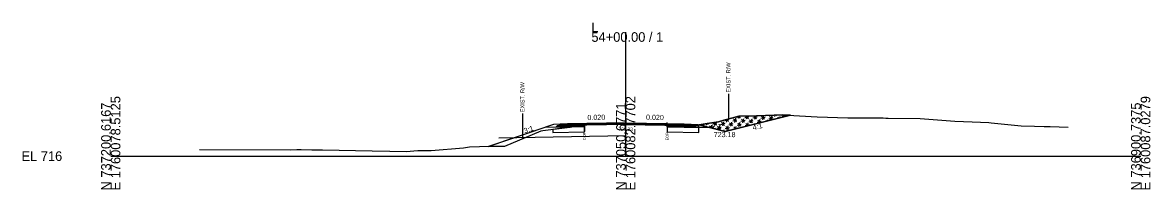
# Model space of a CAD drawing. Extents: x -26 to 4303, y -10 to 9577.
# Drawn here: x 3974.3 to 4302.8, y 3990.3 to 4038.9 of the extents above; entities that cross this region are included whole.
import ezdxf

# ---------------------------------------------------------------- set-up
doc = ezdxf.new("R2010")
doc.units = 0
for name, color, linetype in [('Default', 7, 'Continuous'), ('Exist CMT Pavement', 7, 'Continuous'), ('Old_Level_2', 7, 'Continuous'), ('Pattern 3', 7, 'Continuous'), ('Prop CMT Conc Surface', 7, 'Continuous'), ('Prop CMT Concrete Structures', 7, 'Continuous'), ('Prop CMT Concrete Wall', 7, 'Continuous'), ('Prop CMT Pvmt Course 1', 7, 'Continuous'), ('Prop CMT Pvmt Course 1 CG', 7, 'Continuous'), ('Prop CMT Pvmt Course 2', 7, 'Continuous'), ('Prop CMT Pvmt Course 2 Wedge', 7, 'Continuous'), ('Prop CMT Pvmt Course 3', 7, 'Continuous'), ('Prop CMT Pvmt Surface', 7, 'Continuous'), ('Prop CMT Pvmt Surface Shoulder', 7, 'Continuous'), ('Prop CMT Pvmt Wedge Surface 1', 7, 'Continuous'), ('Prop CMT Pvmt Wedge Surface 2', 7, 'Continuous'), ('Prop CMT Pvmt Wedge Surface 3', 7, 'Continuous'), ('Prop CMT Shld Paved Course 1', 7, 'Continuous'), ('Prop CMT Shld Paved Course 2', 7, 'Continuous'), ('Prop CMT Shld Paved Course 3', 7, 'Continuous'), ('Prop CMT Slope Grass', 7, 'Continuous'), ('Prop CMT Subgrade Earthwork', 7, 'Continuous'), ('Prop Road Sect_ Recs - UC Shallow (Outline)', 7, 'Continuous'), ('Prop Shade Light', 7, 'Continuous'), ('Prop XS DDE Elevations', 7, 'Continuous'), ('Prop XS Ditch Standard Text', 7, 'Continuous'), ('Prop XS Hydro Elevations', 7, 'Continuous'), ('Prop XS SE Text', 7, 'Continuous'), ('Prop XS Side Slope Text', 7, 'Continuous'), ('Prop XS Wedging', 7, 'Continuous'), ('Scratch_Level_2', 7, 'Continuous'), ('Scratch_Level_6', 7, 'Continuous')]:
    doc.layers.add(name, color=color, linetype=linetype)

msp = doc.modelspace()

# ---------------------------------------------------------------- linework, layer by layer
at = {"layer": 'Exist CMT Pavement'}
for points in [[(4150, 4009.72), (4133, 4009.38)], [(4150, 4009.72), (4167, 4009.38)]]:
    msp.add_lwpolyline(points, dxfattribs=at)
at = {"layer": 'Old_Level_2'}
for p, q in [((4150, 4000), (4150, 4036.09)), ((4150, 4000), (4150, 4036.09)), ((4000, 4000), (4150, 4000)), ((4000, 4000), (4150, 4000)), ((4150, 4000), (4300, 4000)), ((4150, 4000), (4300, 4000))]:
    msp.add_line(p, q, dxfattribs=at)
at = {"layer": 'Pattern 3'}
for p, q in [((4182.33, 4011.37), (4183.33, 4011.64)), ((4182.96, 4011.63), (4182.77, 4010.93)), ((4182.85, 4011.61), (4183.37, 4011.09)), ((4184.68, 4011.25), (4185.89, 4011.58)), ((4185.02, 4011.68), (4185.73, 4010.97)), ((4185.36, 4011.69), (4185.12, 4010.81)), ((4187.04, 4011.14), (4188.25, 4011.46)), ((4187.21, 4011.73), (4188.09, 4010.86)), ((4187.76, 4011.75), (4187.48, 4010.69)), ((4189.56, 4011.62), (4190.44, 4010.74)), ((4190.16, 4011.78), (4189.84, 4010.58)), ((4190.99, 4011.82), (4190.96, 4011.7)), ((4191.91, 4011.5), (4192.79, 4010.63)), ((4192.52, 4011.66), (4192.2, 4010.48)), ((4193.41, 4011.93), (4193.31, 4011.58)), ((4193.71, 4011.94), (4193.92, 4011.74)), ((4194.27, 4011.38), (4194.58, 4011.08)), ((4194.87, 4011.55), (4194.76, 4011.12)), ((4195.23, 4011.9), (4195.72, 4012.03)), ((4195.82, 4012.03), (4195.67, 4011.46)), ((4195.87, 4012.02), (4196.27, 4011.62)), ((4135.32, 4008.74), (4135.42, 4008.64)), ((4135.52, 4008.78), (4135.49, 4008.64)), ((4135.69, 4008.64), (4136.08, 4008.75)), ((4137.39, 4008.91), (4137.62, 4008.68)), ((4137.95, 4008.93), (4137.89, 4008.69)), ((4162.47, 4009.02), (4162.38, 4008.69)), ((4162.87, 4008.97), (4162.99, 4008.86)), ((4164.79, 4008.77), (4164.75, 4008.64)), ((4172.06, 4008.98), (4172.14, 4008.9)), ((4172.67, 4009.14), (4172.57, 4008.79)), ((4173.03, 4008.67), (4173.11, 4008.69)), ((4173.57, 4009.45), (4173.46, 4009.05)), ((4173.78, 4009.49), (4174.06, 4009.21)), ((4174.42, 4008.86), (4175.12, 4008.15)), ((4174.48, 4008.31), (4175.46, 4008.58)), ((4175.02, 4009.02), (4174.81, 4008.23)), ((4175.38, 4009.37), (4176.58, 4009.7)), ((4175.71, 4009.8), (4176.42, 4009.09)), ((4176.07, 4009.86), (4175.82, 4008.93)), ((4176.61, 4008.13), (4177.82, 4008.46)), ((4176.77, 4008.74), (4177.66, 4007.85)), ((4177.38, 4008.9), (4177.06, 4007.69)), ((4177.73, 4009.25), (4178.94, 4009.58)), ((4177.89, 4009.86), (4178.78, 4008.97)), ((4178.5, 4010.02), (4178.17, 4008.81)), ((4178.85, 4010.37), (4180.06, 4010.7)), ((4178.97, 4008.02), (4180.18, 4008.34)), ((4179.13, 4008.62), (4180.02, 4007.74)), ((4179.49, 4010.68), (4179.29, 4009.93)), ((4179.35, 4010.64), (4179.9, 4010.09)), ((4179.73, 4008.78), (4179.41, 4007.57)), ((4180.09, 4009.14), (4181.3, 4009.46)), ((4180.25, 4009.74), (4181.13, 4008.85)), ((4180.85, 4009.9), (4180.53, 4008.69)), ((4181.21, 4010.25), (4182.41, 4010.58)), ((4181.33, 4007.9), (4182.53, 4008.22)), ((4181.37, 4010.86), (4182.25, 4009.97)), ((4181.49, 4008.5), (4182.05, 4007.94)), ((4181.97, 4011.02), (4181.65, 4009.81)), ((4182.09, 4008.66), (4181.89, 4007.9)), ((4182.44, 4009.02), (4183.65, 4009.34)), ((4182.61, 4009.62), (4183.49, 4008.74)), ((4183.21, 4009.78), (4182.89, 4008.57)), ((4183.56, 4010.14), (4184.77, 4010.46)), ((4183.73, 4010.74), (4184.61, 4009.86)), ((4184.33, 4010.9), (4184.01, 4009.69)), ((4184.45, 4008.54), (4184.45, 4008.54)), ((4184.8, 4008.9), (4186.01, 4009.22)), ((4184.96, 4009.5), (4185.63, 4008.84)), ((4185.57, 4009.66), (4185.33, 4008.76)), ((4185.92, 4010.02), (4187.13, 4010.34)), ((4186.08, 4010.62), (4186.97, 4009.74)), ((4186.69, 4010.78), (4186.36, 4009.58)), ((4187.32, 4009.38), (4187.42, 4009.29)), ((4187.92, 4009.55), (4187.89, 4009.4)), ((4188.28, 4009.9), (4189.48, 4010.22)), ((4188.44, 4010.5), (4189.21, 4009.73)), ((4189.04, 4010.66), (4188.76, 4009.62)), ((4189.4, 4011.02), (4190.6, 4011.34)), ((4190.8, 4010.38), (4191, 4010.18)), ((4191.4, 4010.55), (4191.32, 4010.26)), ((4191.75, 4010.9), (4192.96, 4011.22)), ((4178.01, 4007.5), (4178.11, 4007.4)), ((4178.62, 4007.66), (4178.52, 4007.3)), ((4178.95, 4007.19), (4179.06, 4007.22))]:
    msp.add_line(p, q, dxfattribs=at)
for points in [[(4197.95, 4011.92), (4179, 4007.18), (4171.4, 4009.08), (4173.75, 4009.49), (4176.98, 4010), (4178.62, 4010.43), (4179.73, 4010.74), (4182.93, 4011.63), (4188.12, 4011.76), (4190.67, 4011.81), (4195.71, 4012.03), (4197.23, 4011.96)], [(4134.06, 4008.53), (4137.95, 4008.61), (4137.95, 4009.19)], [(4167.16, 4008.5), (4162.07, 4008.61), (4162.07, 4009.06)], [(4171.31, 4008.42), (4171.31, 4009.07), (4167.95, 4008.49)]]:
    msp.add_lwpolyline(points, close=True, dxfattribs=at)
at = {"layer": 'Prop CMT Conc Surface'}
for points in [[(4137.95, 4009.23), (4133, 4009.13)], [(4133, 4009.13), (4133, 4008.92)], [(4133, 4008.92), (4137.95, 4009.02)], [(4137.95, 4009.02), (4137.95, 4009.23)], [(4162.07, 4009.02), (4162.07, 4009.23)], [(4162.07, 4009.23), (4167, 4009.13)], [(4167, 4008.92), (4162.07, 4009.02)], [(4167, 4009.13), (4167, 4008.92)]]:
    msp.add_lwpolyline(points, dxfattribs=at)
at = {"layer": 'Prop CMT Concrete Structures'}
for points in [[(4133, 4009.13), (4133, 4009.38)], [(4137.95, 4009.23), (4133, 4009.13)], [(4150, 4009.6), (4137.95, 4009.36)], [(4137.95, 4009.36), (4137.95, 4009.23)], [(4150, 4009.6), (4162.07, 4009.36)], [(4162.07, 4009.36), (4162.07, 4009.23)], [(4162.07, 4009.23), (4167, 4009.13)], [(4167, 4009.13), (4167, 4009.38)]]:
    msp.add_lwpolyline(points, dxfattribs=at)
at = {"layer": 'Prop CMT Pvmt Course 1'}
for points in [[(4137.95, 4009.02), (4133, 4008.92)], [(4133, 4008.92), (4133, 4008.59)], [(4133, 4008.59), (4137.95, 4008.69)], [(4137.95, 4008.69), (4137.95, 4009.02)], [(4162.07, 4009.02), (4167, 4008.92)], [(4162.07, 4008.69), (4162.07, 4009.02)], [(4167, 4008.59), (4162.07, 4008.69)], [(4167, 4008.92), (4167, 4008.59)]]:
    msp.add_lwpolyline(points, dxfattribs=at)
at = {"layer": 'Prop CMT Pvmt Course 2'}
for points in [[(4133, 4009.38), (4131, 4009.34), (4130.74, 4009.09)], [(4130.74, 4009.09), (4133, 4009.13)], [(4133, 4009.13), (4133, 4009.38)], [(4167, 4009.38), (4169, 4009.34), (4169.26, 4009.09)], [(4167, 4009.13), (4167, 4009.38)], [(4169.26, 4009.09), (4167, 4009.13)]]:
    msp.add_lwpolyline(points, dxfattribs=at)
at = {"layer": 'Prop CMT Pvmt Course 2 Wedge'}
for points in [[(4169, 4009.34), (4171, 4009.18), (4179, 4007.18), (4197.95, 4011.92)], [(4131, 4009.34), (4129, 4009.18), (4110.1, 4002.85)]]:
    msp.add_lwpolyline(points, dxfattribs=at)
at = {"layer": 'Prop CMT Pvmt Course 3'}
for points in [[(4133, 4009.13), (4130.74, 4009.09), (4130.53, 4008.87)], [(4130.53, 4008.87), (4133, 4008.92)], [(4133, 4008.92), (4133, 4009.13)], [(4167, 4009.13), (4169.26, 4009.09), (4169.47, 4008.87)], [(4167, 4008.92), (4167, 4009.13)], [(4169.47, 4008.87), (4167, 4008.92)]]:
    msp.add_lwpolyline(points, dxfattribs=at)
at = {"layer": 'Prop CMT Pvmt Surface'}
for points in [[(4150, 4009.47), (4133, 4009.13)], [(4133, 4009.13), (4133, 4009.38)], [(4150, 4009.47), (4167, 4009.13)], [(4167, 4009.13), (4167, 4009.38)]]:
    msp.add_lwpolyline(points, dxfattribs=at)
at = {"layer": 'Prop CMT Pvmt Surface Shoulder'}
for points in [[(4137.95, 4009.19), (4138.02, 4009.2), (4139.05, 4009.23), (4139.4, 4009.23), (4140.63, 4009.24), (4141.27, 4009.24), (4141.92, 4009.25), (4143.1, 4009.27), (4144.42, 4009.3), (4145.53, 4009.31), (4146.93, 4009.32), (4147.96, 4009.32), (4149.43, 4009.34), (4149.59, 4009.34), (4150, 4009.33)], [(4150, 4009.33), (4150.4, 4009.32), (4151.53, 4009.31), (4151.93, 4009.3), (4152.83, 4009.29), (4154.43, 4009.27), (4155.26, 4009.26), (4156.93, 4009.22), (4157.69, 4009.2), (4159.43, 4009.16), (4159.6, 4009.16), (4160.97, 4009.11), (4161.48, 4009.09), (4161.88, 4009.08), (4162.07, 4009.06)]]:
    msp.add_lwpolyline(points, dxfattribs=at)
at = {"layer": 'Prop CMT Pvmt Wedge Surface 1'}
for p, q in [((4133.02, 4008.47), (4126.47, 4008.33)), ((4137.95, 4008.56), (4133.02, 4008.47)), ((4162.07, 4008.56), (4166.98, 4008.47)), ((4166.98, 4008.47), (4174.47, 4008.32))]:
    msp.add_line(p, q, dxfattribs=at)
for points in [[(4137.95, 4008.56), (4137.95, 4009.19)], [(4162.07, 4008.56), (4162.07, 4009.06)]]:
    msp.add_lwpolyline(points, dxfattribs=at)
at = {"layer": 'Prop CMT Pvmt Wedge Surface 2'}
for points in [[(4137.95, 4009.36), (4138.02, 4009.36), (4139.05, 4009.38), (4139.4, 4009.38), (4140.63, 4009.41), (4141.27, 4009.42), (4141.92, 4009.44), (4143.1, 4009.46), (4144.42, 4009.49), (4145.53, 4009.51), (4146.93, 4009.54), (4147.96, 4009.56), (4149.43, 4009.59), (4149.59, 4009.59), (4150, 4009.6)], [(4150, 4009.47), (4149.59, 4009.46), (4149.43, 4009.46), (4147.96, 4009.43), (4146.93, 4009.41), (4145.53, 4009.38), (4144.42, 4009.36), (4143.1, 4009.33), (4141.92, 4009.31), (4141.27, 4009.3), (4140.63, 4009.28), (4139.4, 4009.26), (4139.05, 4009.25), (4138.02, 4009.23), (4137.95, 4009.23)], [(4137.95, 4009.23), (4137.95, 4009.36)], [(4150, 4009.6), (4150, 4009.47)], [(4150, 4009.6), (4150.4, 4009.59), (4151.53, 4009.57), (4151.93, 4009.56), (4152.83, 4009.54), (4154.43, 4009.51), (4155.26, 4009.49), (4156.93, 4009.46), (4157.69, 4009.44), (4159.43, 4009.41), (4159.6, 4009.4), (4160.97, 4009.38), (4161.48, 4009.37), (4161.88, 4009.36), (4162.07, 4009.36)], [(4162.07, 4009.23), (4161.88, 4009.23), (4161.48, 4009.24), (4160.97, 4009.25), (4159.6, 4009.28), (4159.43, 4009.28), (4157.69, 4009.32), (4156.93, 4009.33), (4155.26, 4009.37), (4154.43, 4009.38), (4152.83, 4009.42), (4151.93, 4009.43), (4151.53, 4009.44), (4150.4, 4009.46), (4150, 4009.47)], [(4162.07, 4009.36), (4162.07, 4009.23)]]:
    msp.add_lwpolyline(points, dxfattribs=at)
at = {"layer": 'Prop CMT Pvmt Wedge Surface 3'}
for points in [[(4137.95, 4009.23), (4138.02, 4009.23), (4139.05, 4009.25), (4139.4, 4009.26), (4140.63, 4009.28), (4141.27, 4009.3), (4141.92, 4009.31), (4143.1, 4009.33), (4144.42, 4009.36), (4145.53, 4009.38), (4146.93, 4009.41), (4147.96, 4009.43), (4149.43, 4009.46), (4149.59, 4009.46), (4150, 4009.47)], [(4150, 4009.33), (4149.59, 4009.34), (4149.43, 4009.34), (4147.96, 4009.32), (4146.93, 4009.32), (4145.53, 4009.31), (4144.42, 4009.3), (4143.1, 4009.27), (4141.92, 4009.25), (4141.27, 4009.24), (4140.63, 4009.24), (4139.4, 4009.23), (4139.05, 4009.23), (4138.02, 4009.2), (4137.95, 4009.19)], [(4137.95, 4009.19), (4137.95, 4009.23)], [(4150, 4009.47), (4150, 4009.33)], [(4150, 4009.47), (4150.4, 4009.46), (4151.53, 4009.44), (4151.93, 4009.43), (4152.83, 4009.42), (4154.43, 4009.38), (4155.26, 4009.37), (4156.93, 4009.33), (4157.69, 4009.32), (4159.43, 4009.28), (4159.6, 4009.28), (4160.97, 4009.25), (4161.48, 4009.24), (4161.88, 4009.23), (4162.07, 4009.23)], [(4162.07, 4009.06), (4161.88, 4009.08), (4161.48, 4009.09), (4160.97, 4009.11), (4159.6, 4009.16), (4159.43, 4009.16), (4157.69, 4009.2), (4156.93, 4009.22), (4155.26, 4009.26), (4154.43, 4009.27), (4152.83, 4009.29), (4151.93, 4009.3), (4151.53, 4009.31), (4150.4, 4009.32), (4150, 4009.33)], [(4162.07, 4009.23), (4162.07, 4009.06)]]:
    msp.add_lwpolyline(points, dxfattribs=at)
at = {"layer": 'Prop CMT Shld Paved Course 1'}
for points in [[(4133, 4008.92), (4133, 4009.38)], [(4150, 4009.26), (4133, 4008.92)], [(4150, 4009.26), (4167, 4008.92)], [(4167, 4008.92), (4167, 4009.38)]]:
    msp.add_lwpolyline(points, dxfattribs=at)
at = {"layer": 'Prop CMT Shld Paved Course 2'}
for points in [[(4133, 4009.38), (4131, 4009.34)], [(4167, 4009.38), (4169, 4009.34)]]:
    msp.add_lwpolyline(points, dxfattribs=at)
at = {"layer": 'Prop CMT Shld Paved Course 3'}
for points in [[(4150, 4009.72), (4133, 4009.38)], [(4133, 4009.38), (4133, 4009.13)], [(4133, 4009.13), (4137.95, 4009.23)], [(4137.95, 4009.36), (4150, 4009.6)], [(4137.95, 4009.23), (4137.95, 4009.36)], [(4150, 4009.47), (4150, 4009.72)], [(4150, 4009.72), (4167, 4009.38)], [(4150, 4009.6), (4150, 4009.47), (4150, 4009.47)], [(4162.07, 4009.36), (4150, 4009.6)], [(4162.07, 4009.23), (4162.07, 4009.36)], [(4167, 4009.13), (4162.07, 4009.23)], [(4167, 4009.38), (4167, 4009.13)]]:
    msp.add_lwpolyline(points, dxfattribs=at)
at = {"layer": 'Prop CMT Slope Grass'}
msp.add_lwpolyline([(4025.84, 4001.95), (4052.24, 4001.87), (4054.23, 4001.89), (4055.49, 4001.91), (4058.55, 4001.87), (4061.65, 4001.83), (4076.1, 4001.54), (4081.29, 4001.46), (4086, 4001.39), (4089.41, 4001.67), (4093.28, 4001.67), (4102.77, 4002.42), (4104.52, 4002.69), (4107.39, 4002.78), (4110.84, 4002.87), (4114.81, 4002.93), (4122.87, 4006.3), (4125.39, 4007.38), (4125.85, 4007.42), (4132.13, 4008.2), (4138.02, 4009.2), (4139.05, 4009.23), (4139.4, 4009.23), (4140.63, 4009.24), (4141.27, 4009.24), (4141.92, 4009.25), (4143.1, 4009.27), (4144.42, 4009.3), (4145.83, 4009.31), (4146.93, 4009.32), (4147.96, 4009.32), (4149.59, 4009.34), (4150, 4009.33), (4150.4, 4009.32), (4151.53, 4009.31), (4151.93, 4009.3), (4152.83, 4009.29), (4154.43, 4009.27), (4155.26, 4009.26), (4156.93, 4009.22), (4157.69, 4009.2), (4159.6, 4009.16), (4160.97, 4009.11), (4161.48, 4009.09), (4161.88, 4009.08), (4164.58, 4008.83), (4167.67, 4008.44), (4173.75, 4009.49), (4176.98, 4010), (4178.62, 4010.43), (4179.73, 4010.74), (4182.93, 4011.63), (4188.12, 4011.76), (4190.67, 4011.81), (4195.71, 4012.03), (4197.23, 4011.96), (4205.72, 4011.47), (4214.69, 4011.17), (4215.72, 4011.15), (4224.99, 4011.11), (4225.73, 4011.1), (4226.42, 4011.08), (4235.73, 4010.98), (4245.88, 4010.17), (4250.87, 4009.96), (4255.74, 4009.76), (4256.4, 4009.71), (4265.2, 4008.84), (4269.03, 4008.71), (4271.87, 4008.67), (4273.59, 4008.67), (4278.86, 4008.44)], dxfattribs=at)
at = {"layer": 'Prop CMT Subgrade Earthwork'}
for points in [[(4133, 4008.92), (4130.53, 4008.87), (4130.03, 4008.86), (4129.69, 4008.52)], [(4129.69, 4008.52), (4133, 4008.59)], [(4133, 4008.59), (4133, 4008.92)], [(4167, 4008.92), (4169.47, 4008.87), (4169.97, 4008.86), (4170.31, 4008.52)], [(4167, 4008.59), (4167, 4008.92)], [(4170.31, 4008.52), (4167, 4008.59)]]:
    msp.add_lwpolyline(points, dxfattribs=at)
at = {"layer": 'Prop Road Sect_ Recs - UC Shallow (Outline)'}
for points in [[(4128.72, 4006.92), (4137.98, 4007.11), (4137.95, 4008.61), (4134.06, 4008.53), (4133.2, 4008.38), (4128.72, 4007.78)], [(4162.04, 4007.11), (4171.28, 4006.92), (4171.31, 4008.42), (4167.95, 4008.49), (4167.67, 4008.44), (4167.42, 4008.47), (4167.16, 4008.5), (4165.98, 4008.53), (4162.07, 4008.61)]]:
    msp.add_lwpolyline(points, close=True, dxfattribs=at)
at = {"layer": 'Prop Shade Light'}
for p, q in [((4132.13, 4008.2), (4128.72, 4007.78)), ((4134.06, 4008.53), (4132.13, 4008.2)), ((4137.95, 4008.61), (4134.06, 4008.53)), ((4137.98, 4007.11), (4137.95, 4008.61)), ((4162.07, 4008.61), (4162.04, 4007.11)), ((4167.16, 4008.5), (4162.07, 4008.61)), ((4167.67, 4008.44), (4167.16, 4008.5)), ((4167.95, 4008.49), (4167.67, 4008.44)), ((4170.31, 4008.44), (4167.95, 4008.49)), ((4171.31, 4008.42), (4170.31, 4008.44)), ((4171.28, 4006.92), (4171.31, 4008.42)), ((4128.72, 4007.78), (4128.72, 4006.92)), ((4128.72, 4006.92), (4137.98, 4007.11)), ((4162.04, 4007.11), (4171.28, 4006.92))]:
    msp.add_line(p, q, dxfattribs=at)
at = {"layer": 'Prop XS DDE Elevations'}
for points in [[(4171.4, 4009.08), (4174.47, 4008.32), (4179, 4007.18), (4197.95, 4011.92), (4197.23, 4011.96), (4195.71, 4012.03), (4190.67, 4011.81), (4188.12, 4011.76), (4182.93, 4011.63), (4179.73, 4010.74), (4178.62, 4010.43), (4176.98, 4010), (4173.75, 4009.49)], [(4125.85, 4007.42), (4132.13, 4008.2), (4133.79, 4008.48), (4133.02, 4008.47), (4126.47, 4008.33), (4110.1, 4002.85), (4110.84, 4002.87), (4114.81, 4002.93), (4122.87, 4006.3), (4125.39, 4007.38)], [(4133.79, 4008.48), (4137.95, 4009.19), (4137.95, 4008.56)], [(4147.96, 4009.32), (4149.43, 4009.34), (4149.59, 4009.34)], [(4157.69, 4009.2), (4159.6, 4009.16), (4159.43, 4009.16)], [(4162.07, 4009.06), (4164.58, 4008.83), (4167.56, 4008.45), (4166.98, 4008.47), (4162.07, 4008.56)], [(4167.56, 4008.45), (4167.67, 4008.44), (4167.73, 4008.45)], [(4171.4, 4009.08), (4174.47, 4008.32), (4167.73, 4008.45)]]:
    msp.add_lwpolyline(points, close=True, dxfattribs=at)
at = {"layer": 'Prop XS Ditch Standard Text'}
for p, q in [((4179.92, 4018.19), (4179.92, 4010.79)), ((4119.92, 4012.46), (4119.92, 4005.06)), ((4137.95, 4009.19), (4137.95, 4007.14)), ((4162.07, 4009.06), (4162.07, 4007.01))]:
    msp.add_line(p, q, dxfattribs=at)
at = {"layer": 'Prop XS Wedging'}
for p, q in [((4137.95, 4009.19), (4137.95, 4009.62)), ((4137.95, 4009.36), (4137.95, 4009.19)), ((4162.07, 4009.06), (4162.07, 4009.77)), ((4162.07, 4009.06), (4162.07, 4009.36))]:
    msp.add_line(p, q, dxfattribs=at)
for points in [[(4150, 4009.6), (4133, 4009.26)], [(4150, 4009.6), (4150, 4009.6), (4137.95, 4009.36)], [(4137.95, 4009.19), (4138.02, 4009.2), (4139.05, 4009.23), (4139.4, 4009.23), (4140.63, 4009.24), (4141.27, 4009.24), (4141.92, 4009.25), (4143.1, 4009.27), (4144.42, 4009.3), (4145.83, 4009.31), (4146.93, 4009.32), (4147.96, 4009.32), (4149.59, 4009.34), (4150, 4009.33), (4150.4, 4009.32), (4151.53, 4009.31), (4151.93, 4009.3), (4152.83, 4009.29), (4154.43, 4009.27), (4155.26, 4009.26), (4156.93, 4009.22), (4157.69, 4009.2), (4159.6, 4009.16), (4160.97, 4009.11), (4161.48, 4009.09), (4161.88, 4009.08), (4162.07, 4009.06)], [(4137.95, 4009.19), (4137.95, 4009.19)], [(4150, 4009.6), (4167, 4009.26)], [(4162.07, 4009.36), (4150, 4009.6), (4150, 4009.6)]]:
    msp.add_lwpolyline(points, dxfattribs=at)
at = {"layer": 'Scratch_Level_2'}
for p, q in [((4126.46, 4008.33), (4110, 4002.85)), ((4163.94, 4008.66), (4163.94, 4008.65))]:
    msp.add_line(p, q, dxfattribs=at)
at = {"layer": 'Scratch_Level_6'}
msp.add_lwpolyline([(4150, 4005.93), (4113.03, 4005.19)], dxfattribs=at)

# ---------------------------------------------------------------- texts
at = {"layer": 'Default'}
msp.add_text('-', height=0.0001, dxfattribs=at).set_placement((4000, 4000))
at = {"layer": 'Old_Level_2'}
for s, p in [('L', (4140, 4036.09)), ('L', (4140, 4036.09)), ('54+00.00 / 1', (4140, 4033.29)), ('54+00.00 / 1', (4140, 4033.29)), ('EL 716', (3974, 3998.6)), ('EL 716', (3974, 3998.6))]:
    msp.add_text(s, height=2.8, dxfattribs=at).set_placement(p)
for s, p in [('N 737200.6167', (4000, 3990)), ('N 737200.6167', (4000, 3990)), ('E 1760078.5125', (4002.8, 3990)), ('E 1760078.5125', (4002.8, 3990)), ('N 737050.6771', (4150, 3990)), ('N 737050.6771', (4150, 3990)), ('E 1760082.7702', (4152.8, 3990)), ('E 1760082.7702', (4152.8, 3990)), ('N 736900.7375', (4300, 3990)), ('N 736900.7375', (4300, 3990)), ('E 1760087.0279', (4302.8, 3990)), ('E 1760087.0279', (4302.8, 3990))]:
    msp.add_text(s, height=2.8, rotation=90, dxfattribs=at).set_placement(p)
at = {"layer": 'Prop CMT Concrete Wall'}
msp.add_text('3:1', height=1.5, rotation=19.1447, dxfattribs=at).set_placement((4120.6, 4006.59))
at = {"layer": 'Prop CMT Pvmt Course 1 CG'}
msp.add_text('725.33', height=1, dxfattribs=at).set_placement((4147.88, 4007.33))
at = {"layer": 'Prop XS Ditch Standard Text'}
for s, height, p in [('EXIST. R/W', 1.181, (4180.51, 4018.5)), ('EXIST. R/W', 1.181, (4120.51, 4012.77)), ('EOP', 0.787, (4138.35, 4004.74)), ('EOP', 0.787, (4162.46, 4004.61))]:
    msp.add_text(s, height=height, rotation=90, dxfattribs=at).set_placement(p)
at = {"layer": 'Prop XS Hydro Elevations'}
msp.add_text('723.18', height=1.5, dxfattribs=at).set_placement((4175.64, 4005.53))
at = {"layer": 'Prop XS SE Text'}
for rotation, p in [(1.1458, (4138.86, 4010.5)), (358.8542, (4155.9, 4010.6))]:
    msp.add_text('0.020', height=1.5, rotation=rotation, dxfattribs=at).set_placement(p)
at = {"layer": 'Prop XS Side Slope Text'}
for rotation, p in [(345.9638, (4174.83, 4008.46)), (14.0362, (4187.17, 4007.55))]:
    msp.add_text('4:1', height=1.5, rotation=rotation, dxfattribs=at).set_placement(p)

doc.saveas('drawing.dxf')
